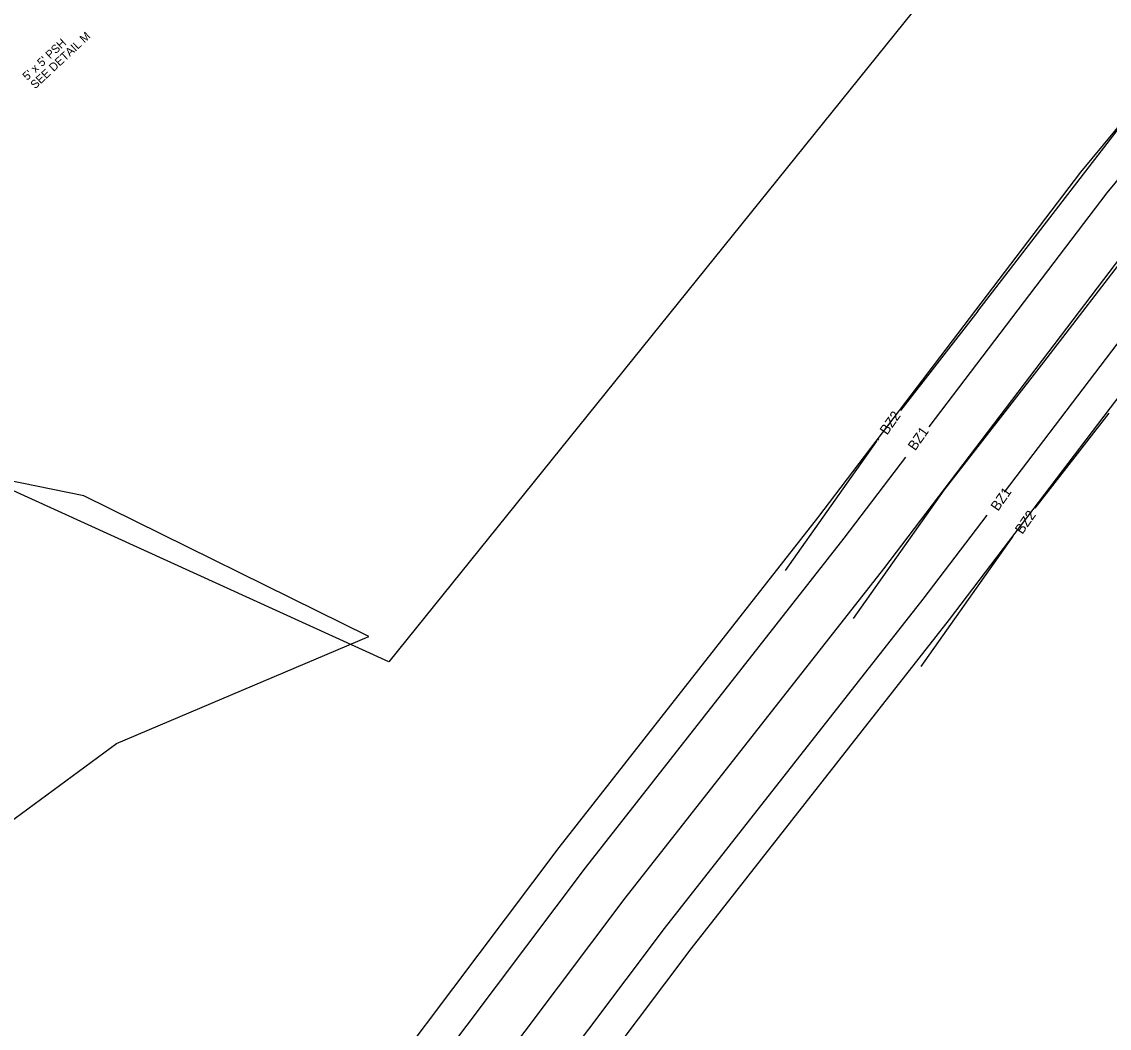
# Model space of a CAD drawing. Extents: x 2384780 to 2405432, y 547869 to 573706.
# Drawn here: x 2397544 to 2398198, y 558336 to 558941 of the extents above; entities that cross this region are included whole.
import ezdxf

# ---------------------------------------------------------------- set-up
doc = ezdxf.new("R2010")
doc.units = 0
for name, color, linetype in [('Old_Level_5', 7, 'Continuous'), ('Old_Level_6', 7, 'Continuous'), ('Old_Level_62', 7, 'Continuous'), ('Prop Buffer Zone 1', 7, 'Continuous'), ('Prop Buffer Zone 2', 7, 'Continuous')]:
    doc.layers.add(name, color=color, linetype=linetype)

msp = doc.modelspace()

# ---------------------------------------------------------------- linework, layer by layer
at = {"layer": 'Old_Level_6'}
for p, q in [((2398261.67, 558870.2), (2398158.46, 558736.12)), ((2398158.46, 558736.12), (2398098.6, 558659.18)), ((2398098.6, 558659.18), (2398044.07, 558582.01))]:
    msp.add_line(p, q, dxfattribs=at)
msp.add_lwpolyline([(2398714.6, 559417.4), (2398692.62, 559401.34), (2398675.69, 559389.15), (2398644.79, 559357.42), (2398634.71, 559350.36), (2398626.87, 559344.06), (2398617.88, 559336.75), (2398606.3, 559326.01), (2398597.75, 559317.84), (2398594.19, 559312.41), (2398523.72, 559215.14), (2398416.1, 559070.93), (2398302.68, 558919.12), (2398219.96, 558819.3), (2398062.24, 558612.01), (2397906.77, 558413.99), (2397747.06, 558201.74), (2397598.91, 558004.2), (2397495.88, 557873.07), (2397449.27, 557810.14)], dxfattribs=at)
at = {"layer": 'Old_Level_62'}
msp.add_lwpolyline([(2397220.17, 559463.12), (2398218.71, 559471.56), (2398237.6, 559142.52), (2397764.97, 558556.02), (2397466.68, 558691.91), (2397374.16, 558981.45), (2397777.58, 559376.08)], dxfattribs=at)
msp.add_lwpolyline([(2396419.7, 557643.47), (2396682.04, 557796.2), (2396828.18, 557960.29), (2396996.36, 558095.15), (2397094.89, 558211.04), (2397313.65, 558336.89), (2397384.14, 558347.22), (2397601.34, 558506.89), (2397752.86, 558571.29), (2397581.56, 558655.74), (2397315.55, 558710.07), (2397180.39, 558737.03), (2396733.28, 558297.93), (2396405.46, 557985.46), (2396072.95, 557622.86), (2396164.14, 557546.31)], close=True, dxfattribs=at)
at = {"layer": 'Prop Buffer Zone 1'}
for points in [[(2398696.89, 559441.62), (2398675, 559425.62), (2398656.02, 559411.95), (2398625.27, 559380.38), (2398616.69, 559374.37), (2398608, 559367.39), (2398598.19, 559359.41), (2398585.74, 559347.85), (2398574.54, 559337.16), (2398569.48, 559329.43), (2398499.55, 559232.91), (2398392.06, 559088.88), (2398279.1, 558937.68), (2398196.46, 558837.96), (2398089.47, 558697.34)], [(2398732.3, 559393.18), (2398710.23, 559377.06), (2398695.35, 559366.34), (2398664.31, 559334.46), (2398652.73, 559326.36), (2398645.73, 559320.73), (2398637.56, 559314.09), (2398626.87, 559304.16), (2398620.96, 559298.53), (2398618.9, 559295.38), (2398547.89, 559197.36), (2398440.14, 559052.98), (2398326.26, 558900.56), (2398243.45, 558800.63), (2398134.86, 558657.91)], [(2398075.59, 558679.1), (2398038.5, 558630.35), (2397882.99, 558432.27), (2397723.08, 558219.76), (2397575.11, 558022.47), (2397472.02, 557891.27), (2397428.31, 557832.24)], [(2398124.35, 558644.09), (2398085.98, 558593.66), (2397930.56, 558395.7), (2397771.05, 558183.72), (2397622.71, 557985.94), (2397519.73, 557854.88), (2397471.76, 557790.09)]]:
    msp.add_lwpolyline(points, dxfattribs=at)
at = {"layer": 'Prop Buffer Zone 2'}
for p, q in [((2398222.29, 558901.01), (2398118.89, 558766.68)), ((2398118.96, 558766.77), (2398072.58, 558707.16)), ((2398153.51, 558648.33), (2398197.93, 558705.42)), ((2398058.17, 558688.6), (2398003.24, 558610.86)), ((2398059.23, 558690), (2398058.71, 558689.34)), ((2398084.91, 558553.16), (2398139.44, 558630.33)), ((2398138.06, 558628.48), (2398140.28, 558631.33))]:
    msp.add_line(p, q, dxfattribs=at)
for points in [[(2398685.09, 559457.77), (2398663.25, 559441.81), (2398642.91, 559427.16), (2398612.26, 559395.68), (2398604.68, 559390.38), (2398595.43, 559382.94), (2398585.06, 559374.51), (2398572.03, 559362.42), (2398559.06, 559350.04), (2398553.01, 559340.78), (2398483.44, 559244.76), (2398376.04, 559100.84), (2398263.38, 558950.05), (2398180.79, 558850.4), (2398022.68, 558642.58), (2397867.13, 558444.46), (2397707.09, 558231.78), (2397559.25, 558034.65), (2397456.12, 557903.4), (2397414.34, 557846.98)], [(2398744.1, 559377.04), (2398721.98, 559360.87), (2398708.46, 559351.13), (2398677.32, 559319.15), (2398664.74, 559310.35), (2398658.3, 559305.18), (2398650.69, 559298.99), (2398640.58, 559289.6), (2398636.44, 559285.65), (2398635.38, 559284.03), (2398564, 559185.52), (2398456.16, 559041.01), (2398341.98, 558888.18), (2398259.12, 558788.19), (2398101.8, 558581.43), (2397946.42, 558383.51), (2397787.04, 558171.71), (2397638.57, 557973.76), (2397535.64, 557842.75), (2397489.46, 557780.38)]]:
    msp.add_lwpolyline(points, dxfattribs=at)

# ---------------------------------------------------------------- texts
at = {"layer": 'Old_Level_5'}
for s, p in [('SEE DETAIL M', (2397552.36, 558900.02)), ("5' x 5' PSH", (2397547.59, 558905.14))]:
    msp.add_text(s, height=5, rotation=43.00001, dxfattribs=at).set_placement(p)
at = {"layer": 'Prop Buffer Zone 1'}
for p in [(2398081.37, 558682.51), (2398131.15, 558646.2)]:
    msp.add_text('BZ1', height=6, rotation=54.96447, dxfattribs=at).set_placement(p)
at = {"layer": 'Prop Buffer Zone 2'}
for p in [(2398064.46, 558691.96), (2398145.75, 558632.27)]:
    msp.add_text('BZ2', height=6, rotation=54.95117, dxfattribs=at).set_placement(p)

doc.saveas('drawing.dxf')
